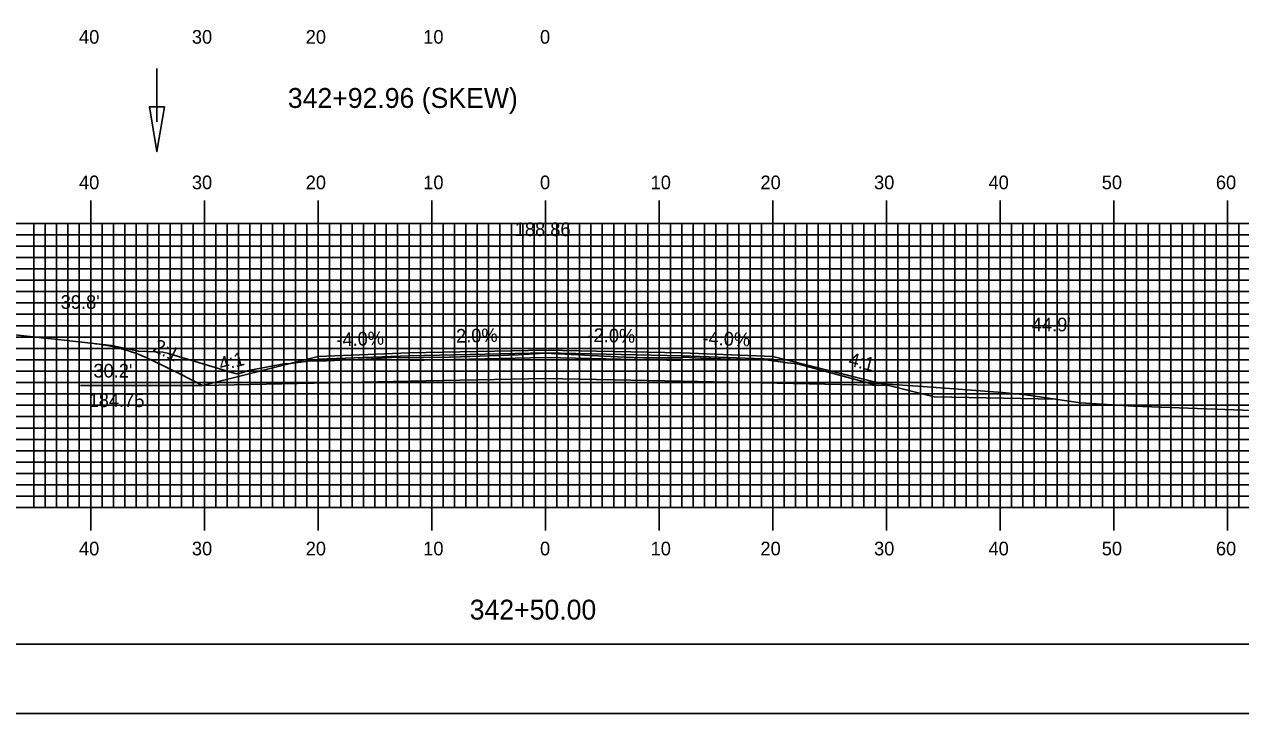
# Model space of a CAD drawing. Extents: x 1825147 to 1825490, y 442591 to 442811.
# Drawn here: x 1825266.5 to 1825373.5, y 442590.5 to 442651.2 of the extents above; entities that cross this region are included whole.
import ezdxf

# ---------------------------------------------------------------- set-up
doc = ezdxf.new("R2010")
doc.units = 0
for name, color, linetype in [('ANNOTATION', 7, 'Continuous'), ('BORDER', 7, 'Continuous'), ('D_Drainage_Ditch_Line', 7, 'Continuous'), ('D_Roadway_Centerline', 7, 'Continuous'), ('D_Roadway_Centerline_Text', 7, 'Continuous'), ('D_Roadway_Edge_Shoulder', 7, 'Continuous'), ('D_Roadway_Edge_TW', 7, 'Continuous'), ('D_Roadway_Pavement', 7, 'Continuous'), ('D_Roadway_SlopeLines', 7, 'Continuous'), ('D_Roadway_SubGrade', 7, 'Continuous'), ('D_Text_Standard', 7, 'Continuous'), ('H_V ANNOTATION', 7, 'Continuous'), ('MAJOR', 7, 'Continuous'), ('MINOR', 7, 'Continuous'), ('PDRAIN', 7, 'Continuous'), ('PLOT BOUNDARY', 7, 'Continuous'), ('S_Roadway_Centerline', 7, 'Continuous')]:
    doc.layers.add(name, color=color, linetype=linetype)

msp = doc.modelspace()

# ---------------------------------------------------------------- linework, layer by layer
at = {"layer": 'ANNOTATION'}
msp.add_line((1825346.54, 442618.42), (1825357.21, 442618.21), dxfattribs=at)
at = {"layer": 'BORDER'}
msp.add_lwpolyline([(1825162.76, 442596.67), (1825482.76, 442596.67), (1825482.76, 442806.67), (1825162.76, 442806.67)], close=True, dxfattribs=at)
at = {"layer": 'D_Drainage_Ditch_Line'}
msp.add_line((1825278.19, 442642.61), (1825278.19, 442647.3), dxfattribs=at)
msp.add_lwpolyline([(1825278.84, 442643.92), (1825277.53, 442643.92), (1825278.19, 442639.98)], close=True, dxfattribs=at)
at = {"layer": 'D_Roadway_Edge_Shoulder'}
for points in [[(1825300.36, 442622.28), (1825292.36, 442621.96), (1825292.36, 442621.71), (1825300.36, 442622.03)], [(1825324.36, 442622.28), (1825332.36, 442621.96), (1825332.36, 442621.71), (1825324.36, 442622.03)]]:
    msp.add_lwpolyline(points, close=True, dxfattribs=at)
at = {"layer": 'D_Roadway_Edge_TW'}
msp.add_lwpolyline([(1825300.36, 442622.03), (1825300.36, 442622.28), (1825312.36, 442622.52), (1825324.36, 442622.28), (1825324.36, 442622.03), (1825312.36, 442622.27)], close=True, dxfattribs=at)
at = {"layer": 'D_Roadway_Pavement'}
msp.add_lwpolyline([(1825300.36, 442621.62), (1825300.36, 442622.03), (1825312.36, 442622.27), (1825324.36, 442622.03), (1825324.36, 442621.62), (1825312.36, 442621.86)], close=True, dxfattribs=at)
at = {"layer": 'D_Roadway_SlopeLines'}
for p, q in [((1825280.19, 442620.42), (1825277.84, 442621.59)), ((1825282.19, 442619.42), (1825280.19, 442620.42))]:
    msp.add_line(p, q, dxfattribs=at)
for points in [[(1825292.36, 442621.96), (1825282.19, 442619.42)], [(1825332.36, 442621.96), (1825346.54, 442618.42)]]:
    msp.add_lwpolyline(points, dxfattribs=at)
msp.add_arc((1825271.13, 442608.17), 15, 63.4349, 83.6525, dxfattribs=at)
at = {"layer": 'D_Roadway_SubGrade'}
msp.add_lwpolyline([(1825300.36, 442619.78), (1825282.19, 442619.42), (1825292.36, 442621.96), (1825292.36, 442621.71), (1825300.36, 442622.03), (1825312.36, 442622.27), (1825324.36, 442622.03), (1825332.36, 442621.71), (1825332.36, 442621.96), (1825342.54, 442619.42), (1825324.36, 442619.78), (1825312.36, 442620.02)], close=True, dxfattribs=at)
at = {"layer": 'MAJOR'}
for p, q in [((1825272.36, 442635.67), (1825272.36, 442633.67)), ((1825282.36, 442635.67), (1825282.36, 442633.67)), ((1825292.36, 442635.67), (1825292.36, 442633.67)), ((1825302.36, 442635.67), (1825302.36, 442633.67)), ((1825312.36, 442635.67), (1825312.36, 442633.67)), ((1825322.36, 442635.67), (1825322.36, 442633.67)), ((1825332.36, 442635.67), (1825332.36, 442633.67)), ((1825342.36, 442635.67), (1825342.36, 442633.67)), ((1825352.36, 442635.67), (1825352.36, 442633.67)), ((1825362.36, 442635.67), (1825362.36, 442633.67)), ((1825372.36, 442635.67), (1825372.36, 442633.67)), ((1825172.36, 442633.67), (1825452.36, 442633.67)), ((1825172.36, 442633.67), (1825452.36, 442633.67)), ((1825272.36, 442608.67), (1825272.36, 442633.67)), ((1825282.36, 442608.67), (1825282.36, 442633.67)), ((1825292.36, 442608.67), (1825292.36, 442633.67)), ((1825302.36, 442608.67), (1825302.36, 442633.67)), ((1825312.36, 442608.67), (1825312.36, 442633.67)), ((1825322.36, 442608.67), (1825322.36, 442633.67)), ((1825332.36, 442608.67), (1825332.36, 442633.67)), ((1825342.36, 442608.67), (1825342.36, 442633.67)), ((1825352.36, 442608.67), (1825352.36, 442633.67)), ((1825362.36, 442608.67), (1825362.36, 442633.67)), ((1825372.36, 442608.67), (1825372.36, 442633.67)), ((1825172.36, 442628.67), (1825452.36, 442628.67)), ((1825172.36, 442623.67), (1825452.36, 442623.67)), ((1825172.36, 442618.67), (1825452.36, 442618.67)), ((1825172.36, 442613.67), (1825452.36, 442613.67)), ((1825172.36, 442608.67), (1825452.36, 442608.67)), ((1825172.36, 442608.67), (1825452.36, 442608.67)), ((1825272.36, 442606.66), (1825272.36, 442608.67)), ((1825282.36, 442606.66), (1825282.36, 442608.67)), ((1825292.36, 442606.66), (1825292.36, 442608.67)), ((1825302.36, 442606.66), (1825302.36, 442608.67)), ((1825312.36, 442606.66), (1825312.36, 442608.67)), ((1825322.36, 442606.66), (1825322.36, 442608.67)), ((1825332.36, 442606.66), (1825332.36, 442608.67)), ((1825342.36, 442606.66), (1825342.36, 442608.67)), ((1825352.36, 442606.66), (1825352.36, 442608.67)), ((1825362.36, 442606.66), (1825362.36, 442608.67)), ((1825372.36, 442606.66), (1825372.36, 442608.67))]:
    msp.add_line(p, q, dxfattribs=at)
at = {"layer": 'MINOR'}
for p, q in [((1825267.36, 442608.67), (1825267.36, 442633.67)), ((1825268.36, 442608.67), (1825268.36, 442633.67)), ((1825269.36, 442608.67), (1825269.36, 442633.67)), ((1825270.36, 442608.67), (1825270.36, 442633.67)), ((1825271.36, 442608.67), (1825271.36, 442633.67)), ((1825273.36, 442608.67), (1825273.36, 442633.67)), ((1825274.36, 442608.67), (1825274.36, 442633.67)), ((1825275.36, 442608.67), (1825275.36, 442633.67)), ((1825276.36, 442608.67), (1825276.36, 442633.67)), ((1825277.36, 442608.67), (1825277.36, 442633.67)), ((1825278.36, 442608.67), (1825278.36, 442633.67)), ((1825279.36, 442608.67), (1825279.36, 442633.67)), ((1825280.36, 442608.67), (1825280.36, 442633.67)), ((1825281.36, 442608.67), (1825281.36, 442633.67)), ((1825283.36, 442608.67), (1825283.36, 442633.67)), ((1825284.36, 442608.67), (1825284.36, 442633.67)), ((1825285.36, 442608.67), (1825285.36, 442633.67)), ((1825286.36, 442608.67), (1825286.36, 442633.67)), ((1825287.36, 442608.67), (1825287.36, 442633.67)), ((1825288.36, 442608.67), (1825288.36, 442633.67)), ((1825289.36, 442608.67), (1825289.36, 442633.67)), ((1825290.36, 442608.67), (1825290.36, 442633.67)), ((1825291.36, 442608.67), (1825291.36, 442633.67)), ((1825293.36, 442608.67), (1825293.36, 442633.67)), ((1825294.36, 442608.67), (1825294.36, 442633.67)), ((1825295.36, 442608.67), (1825295.36, 442633.67)), ((1825296.36, 442608.67), (1825296.36, 442633.67)), ((1825297.36, 442608.67), (1825297.36, 442633.67)), ((1825298.36, 442608.67), (1825298.36, 442633.67)), ((1825299.36, 442608.67), (1825299.36, 442633.67)), ((1825300.36, 442608.67), (1825300.36, 442633.67)), ((1825301.36, 442608.67), (1825301.36, 442633.67)), ((1825303.36, 442608.67), (1825303.36, 442633.67)), ((1825304.36, 442608.67), (1825304.36, 442633.67)), ((1825305.36, 442608.67), (1825305.36, 442633.67)), ((1825306.36, 442608.67), (1825306.36, 442633.67)), ((1825307.36, 442608.67), (1825307.36, 442633.67)), ((1825308.36, 442608.67), (1825308.36, 442633.67)), ((1825309.36, 442608.67), (1825309.36, 442633.67)), ((1825310.36, 442608.67), (1825310.36, 442633.67)), ((1825311.36, 442608.67), (1825311.36, 442633.67)), ((1825313.36, 442608.67), (1825313.36, 442633.67)), ((1825314.36, 442608.67), (1825314.36, 442633.67)), ((1825315.36, 442608.67), (1825315.36, 442633.67)), ((1825316.36, 442608.67), (1825316.36, 442633.67)), ((1825317.36, 442608.67), (1825317.36, 442633.67)), ((1825318.36, 442608.67), (1825318.36, 442633.67)), ((1825319.36, 442608.67), (1825319.36, 442633.67)), ((1825320.36, 442608.67), (1825320.36, 442633.67)), ((1825321.36, 442608.67), (1825321.36, 442633.67)), ((1825323.36, 442608.67), (1825323.36, 442633.67)), ((1825324.36, 442608.67), (1825324.36, 442633.67)), ((1825325.36, 442608.67), (1825325.36, 442633.67)), ((1825326.36, 442608.67), (1825326.36, 442633.67)), ((1825327.36, 442608.67), (1825327.36, 442633.67)), ((1825328.36, 442608.67), (1825328.36, 442633.67)), ((1825329.36, 442608.67), (1825329.36, 442633.67)), ((1825330.36, 442608.67), (1825330.36, 442633.67)), ((1825331.36, 442608.67), (1825331.36, 442633.67)), ((1825333.36, 442608.67), (1825333.36, 442633.67)), ((1825334.36, 442608.67), (1825334.36, 442633.67)), ((1825335.36, 442608.67), (1825335.36, 442633.67)), ((1825336.36, 442608.67), (1825336.36, 442633.67)), ((1825337.36, 442608.67), (1825337.36, 442633.67)), ((1825338.36, 442608.67), (1825338.36, 442633.67)), ((1825339.36, 442608.67), (1825339.36, 442633.67)), ((1825340.36, 442608.67), (1825340.36, 442633.67)), ((1825341.36, 442608.67), (1825341.36, 442633.67)), ((1825343.36, 442608.67), (1825343.36, 442633.67)), ((1825344.36, 442608.67), (1825344.36, 442633.67)), ((1825345.36, 442608.67), (1825345.36, 442633.67)), ((1825346.36, 442608.67), (1825346.36, 442633.67)), ((1825347.36, 442608.67), (1825347.36, 442633.67)), ((1825348.36, 442608.67), (1825348.36, 442633.67)), ((1825349.36, 442608.67), (1825349.36, 442633.67)), ((1825350.36, 442608.67), (1825350.36, 442633.67)), ((1825351.36, 442608.67), (1825351.36, 442633.67)), ((1825353.36, 442608.67), (1825353.36, 442633.67)), ((1825354.36, 442608.67), (1825354.36, 442633.67)), ((1825355.36, 442608.67), (1825355.36, 442633.67)), ((1825356.36, 442608.67), (1825356.36, 442633.67)), ((1825357.36, 442608.67), (1825357.36, 442633.67)), ((1825358.36, 442608.67), (1825358.36, 442633.67)), ((1825359.36, 442608.67), (1825359.36, 442633.67)), ((1825360.36, 442608.67), (1825360.36, 442633.67)), ((1825361.36, 442608.67), (1825361.36, 442633.67)), ((1825363.36, 442608.67), (1825363.36, 442633.67)), ((1825364.36, 442608.67), (1825364.36, 442633.67)), ((1825365.36, 442608.67), (1825365.36, 442633.67)), ((1825366.36, 442608.67), (1825366.36, 442633.67)), ((1825367.36, 442608.67), (1825367.36, 442633.67)), ((1825368.36, 442608.67), (1825368.36, 442633.67)), ((1825369.36, 442608.67), (1825369.36, 442633.67)), ((1825370.36, 442608.67), (1825370.36, 442633.67)), ((1825371.36, 442608.67), (1825371.36, 442633.67)), ((1825373.36, 442608.67), (1825373.36, 442633.67)), ((1825172.36, 442632.67), (1825452.36, 442632.67)), ((1825172.36, 442631.67), (1825452.36, 442631.67)), ((1825172.36, 442630.67), (1825452.36, 442630.67)), ((1825172.36, 442629.67), (1825452.36, 442629.67)), ((1825172.36, 442627.67), (1825452.36, 442627.67)), ((1825172.36, 442626.67), (1825452.36, 442626.67)), ((1825172.36, 442625.67), (1825452.36, 442625.67)), ((1825172.36, 442624.67), (1825452.36, 442624.67)), ((1825172.36, 442622.67), (1825452.36, 442622.67)), ((1825172.36, 442621.67), (1825452.36, 442621.67)), ((1825172.36, 442620.67), (1825452.36, 442620.67)), ((1825172.36, 442619.67), (1825452.36, 442619.67)), ((1825172.36, 442617.67), (1825452.36, 442617.67)), ((1825172.36, 442616.67), (1825452.36, 442616.67)), ((1825172.36, 442615.67), (1825452.36, 442615.67)), ((1825172.36, 442614.67), (1825452.36, 442614.67)), ((1825172.36, 442612.67), (1825452.36, 442612.67)), ((1825172.36, 442611.67), (1825452.36, 442611.67)), ((1825172.36, 442610.67), (1825452.36, 442610.67)), ((1825172.36, 442609.67), (1825452.36, 442609.67))]:
    msp.add_line(p, q, dxfattribs=at)
at = {"layer": 'PDRAIN'}
msp.add_line((1825271.46, 442619.42), (1825282.19, 442619.42), dxfattribs=at)
at = {"layer": 'PLOT BOUNDARY'}
msp.add_lwpolyline([(1825146.57, 442590.55), (1825486.57, 442590.55), (1825486.57, 442810.55), (1825146.57, 442810.55)], close=True, dxfattribs=at)
at = {"layer": 'S_Roadway_Centerline'}
msp.add_lwpolyline([(1825262.85, 442624.18), (1825268.56, 442623.55), (1825269.22, 442623.48), (1825274.18, 442622.93), (1825276.55, 442622.42), (1825278.7, 442622.35), (1825279.21, 442622.21), (1825285.07, 442620.46), (1825285.22, 442620.42), (1825285.42, 442620.45), (1825286.38, 442620.75), (1825289.34, 442621.31), (1825289.96, 442621.34), (1825291.71, 442621.59), (1825292.4, 442621.55), (1825296.58, 442621.72), (1825299.31, 442621.9), (1825299.38, 442621.84), (1825303.93, 442621.89), (1825304.03, 442621.89), (1825309.96, 442622.12), (1825312.3, 442622.26), (1825319.27, 442621.91), (1825321, 442621.85), (1825324.25, 442621.83), (1825324.57, 442621.91), (1825325.99, 442621.81), (1825330.37, 442621.67), (1825331.75, 442621.67), (1825333.66, 442621.41), (1825334.54, 442621.3), (1825338.88, 442620.14), (1825341.15, 442619.54), (1825341.55, 442619.57), (1825345.56, 442619.33), (1825352.57, 442618.79), (1825354.6, 442618.59), (1825359.43, 442617.88), (1825364.09, 442617.59), (1825395.4, 442616.46)], dxfattribs=at)

# ---------------------------------------------------------------- texts
at = {"layer": 'ANNOTATION'}
for s, rotation, p in [('-4.0%', 2.2906, (1825293.99, 442622.83)), ('-2.0%', 1.1458, (1825303.97, 442623.16)), ('-2.0%', 358.8542, (1825316.05, 442623.25)), ('-4.0%', 357.7094, (1825326.15, 442623.01)), ('2:1', 333.4349, (1825277.75, 442622.48)), ('4:1', 14.0362, (1825283.81, 442620.69)), ('4:1', 345.9638, (1825338.95, 442621.18))]:
    msp.add_text(s, height=1.2, rotation=rotation, dxfattribs=at).set_placement(p)
for s, p in [("30.2'", (1825272.6, 442620.11)), ('184.75', (1825272.18, 442617.51))]:
    msp.add_text(s, height=1.2, dxfattribs=at).set_placement(p)
at = {"layer": 'D_Roadway_Centerline'}
for s in ['C', 'L']:
    msp.add_text(s, height=0.0146, dxfattribs=at).set_placement((1825312.36, 442622.52))
at = {"layer": 'D_Roadway_Centerline_Text'}
msp.add_text('188.86', height=1.2, dxfattribs=at).set_placement((1825309.66, 442632.55))
at = {"layer": 'D_Text_Standard'}
for s, p in [("39.8'", (1825269.72, 442626.15)), ("44.9'", (1825355.14, 442624.17))]:
    msp.add_text(s, height=1.2, dxfattribs=at).set_placement(p)
at = {"layer": 'H_V ANNOTATION'}
for s, height, p in [('40', 1.2, (1825271.33, 442649.47)), ('30', 1.2, (1825281.26, 442649.47)), ('20', 1.2, (1825291.27, 442649.47)), ('10', 1.2, (1825301.61, 442649.47)), ('0', 1.2, (1825311.88, 442649.47)), ('342+92.96 (SKEW)', 1.75, (1825289.7, 442643.82)), ('40', 1.2, (1825271.33, 442636.67)), ('30', 1.2, (1825281.26, 442636.67)), ('20', 1.2, (1825291.27, 442636.67)), ('10', 1.2, (1825301.61, 442636.67)), ('0', 1.2, (1825311.88, 442636.67)), ('10', 1.2, (1825321.61, 442636.67)), ('20', 1.2, (1825331.27, 442636.67)), ('30', 1.2, (1825341.26, 442636.67)), ('40', 1.2, (1825351.33, 442636.67)), ('50', 1.2, (1825361.29, 442636.67)), ('60', 1.2, (1825371.33, 442636.67)), ('40', 1.2, (1825271.33, 442604.47)), ('30', 1.2, (1825281.26, 442604.47)), ('20', 1.2, (1825291.27, 442604.47)), ('10', 1.2, (1825301.61, 442604.47)), ('0', 1.2, (1825311.88, 442604.47)), ('10', 1.2, (1825321.61, 442604.47)), ('20', 1.2, (1825331.27, 442604.47)), ('30', 1.2, (1825341.26, 442604.47)), ('40', 1.2, (1825351.33, 442604.47)), ('50', 1.2, (1825361.29, 442604.47)), ('60', 1.2, (1825371.33, 442604.47)), ('342+50.00', 1.75, (1825305.7, 442598.82))]:
    msp.add_text(s, height=height, dxfattribs=at).set_placement(p)
at = {"layer": 'S_Roadway_Centerline'}
for s, p in [('C', (1825312.29, 442622.26)), ('L', (1825312.29, 442622.25))]:
    msp.add_text(s, height=0.0146, dxfattribs=at).set_placement(p)

doc.saveas('drawing.dxf')
